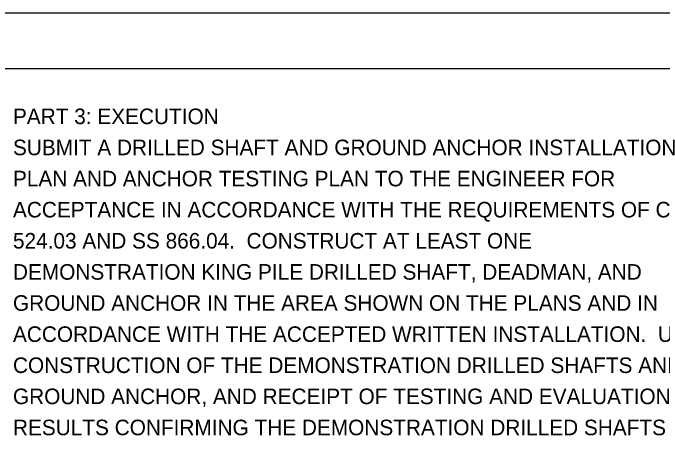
# Model space of a CAD drawing. Extents: x -0.2 to 33.8, y -0.1 to 21.9.
# Drawn here: x 24.94 to 30.78, y 18 to 21.87 of the extents above; entities that cross this region are included whole.
import ezdxf

# ---------------------------------------------------------------- set-up
doc = ezdxf.new("R2010")
doc.units = 0
for name, color, linetype in [('SH_Border', 7, 'Continuous'), ('SH_Cut_Line', 7, 'Continuous'), ('SH_Text', 7, 'Continuous')]:
    doc.layers.add(name, color=color, linetype=linetype)

msp = doc.modelspace()

# ---------------------------------------------------------------- linework, layer by layer
at = {"layer": 'SH_Border'}
msp.add_lwpolyline([(1.7753, 21.368), (33.2753, 21.368), (33.2753, 0.368), (1.7753, 0.368)], close=True, dxfattribs=at)
at = {"layer": 'SH_Cut_Line'}
msp.add_lwpolyline([(-0.2247, 21.868), (33.7753, 21.868), (33.7753, -0.132), (-0.2247, -0.132)], close=True, dxfattribs=at)

# ---------------------------------------------------------------- texts
at = {"layer": 'SH_Text'}
for s, p in [('PART 3: EXECUTION', (24.9353, 20.868)), ('SUBMIT A DRILLED SHAFT AND GROUND ANCHOR INSTALLATION ', (24.9353, 20.588)), ('PLAN AND ANCHOR TESTING PLAN TO THE ENGINEER FOR ', (24.9353, 20.308)), ('ACCEPTANCE IN ACCORDANCE WITH THE REQUIREMENTS OF C&MS ', (24.9353, 20.028)), ('524.03 AND SS 866.04.  CONSTRUCT AT LEAST ONE ', (24.9353, 19.748)), ('DEMONSTRATION KING PILE DRILLED SHAFT, DEADMAN, AND ', (24.9353, 19.468)), ('GROUND ANCHOR IN THE AREA SHOWN ON THE PLANS AND IN ', (24.9353, 19.188)), ('ACCORDANCE WITH THE ACCEPTED WRITTEN INSTALLATION.  UPON ', (24.9353, 18.908)), ('CONSTRUCTION OF THE DEMONSTRATION DRILLED SHAFTS AND ', (24.9353, 18.628)), ('GROUND ANCHOR, AND RECEIPT OF TESTING AND EVALUATION ', (24.9353, 18.348)), ('RESULTS CONFIRMING THE DEMONSTRATION DRILLED SHAFTS AND ', (24.9353, 18.068))]:
    msp.add_text(s, height=0.14, dxfattribs=at).set_placement(p)

doc.saveas('drawing.dxf')
